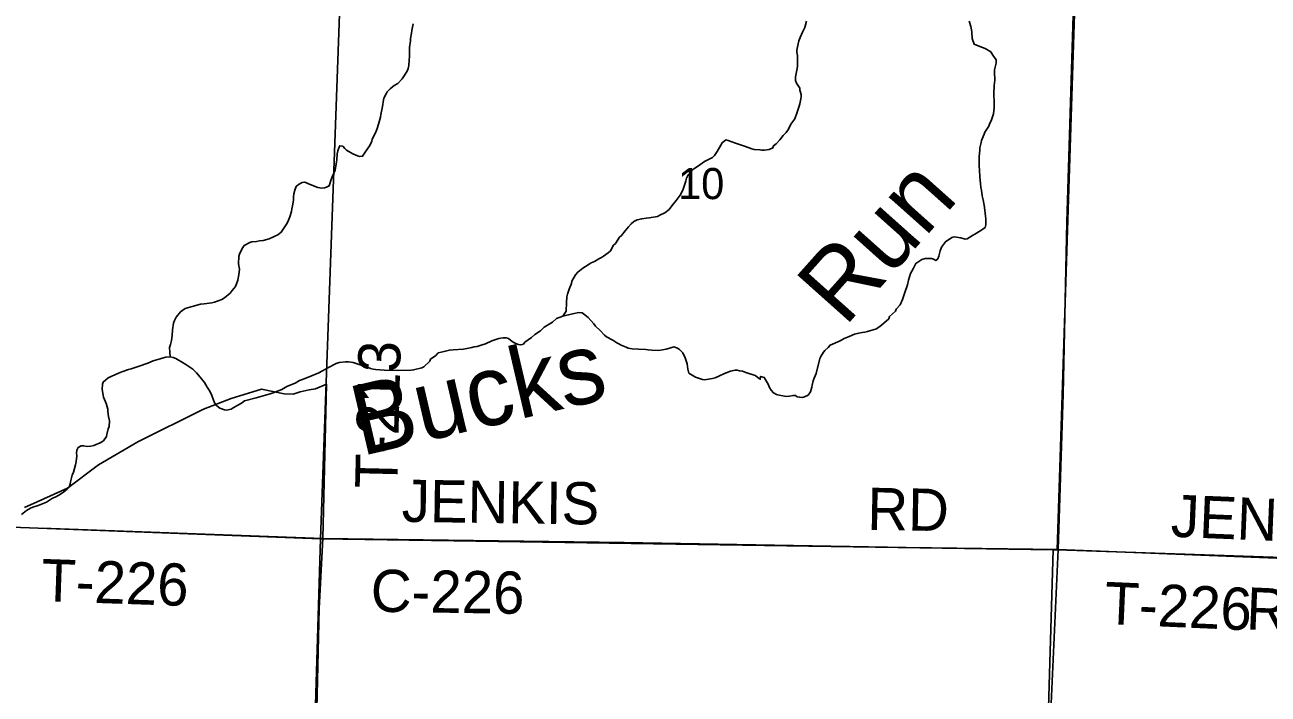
# Model space of a CAD drawing. Extents: x 1310247 to 1552180, y 377264 to 706493.
# Drawn here: x 1327940 to 1336785, y 503189 to 507946 of the extents above; entities that cross this region are included whole.
import ezdxf

# ---------------------------------------------------------------- set-up
doc = ezdxf.new("R2010")
doc.units = 0
for name, color, linetype in [('GM_X_County_Road', 7, 'Continuous'), ('GM_X_County_Road_Text', 7, 'Continuous'), ('GM_X_Minor_River', 7, 'Continuous'), ('GM_X_Minor_River_Text', 7, 'Continuous'), ('GM_X_Section', 7, 'Continuous'), ('GM_X_Section_Text', 7, 'Continuous'), ('GM_X_Township_Road', 7, 'Continuous'), ('GM_X_Township_Road_Text', 7, 'Continuous'), ('GM_X_Township_ROW', 7, 'Continuous')]:
    doc.layers.add(name, color=color, linetype=linetype)

msp = doc.modelspace()

# ---------------------------------------------------------------- linework, layer by layer
at = {"layer": 'GM_X_County_Road'}
for points in [[(1335291.7, 504215.6), (1335326.7, 505321.7), (1335352.9, 506544.2), (1335413.2, 508482.2), (1335437.6, 509275.5), (1335439.3, 509482.1)], [(1329223.9, 497744.5), (1329266.8, 497793.6), (1329294.4, 497850), (1329296.8, 497903.3), (1329271.7, 498120.6), (1329261.1, 498281.9), (1329243.9, 498488.9), (1329167.7, 498785.1), (1329133.2, 498963.3), (1329069.9, 499360.1), (1329046.9, 499679.2), (1329051.1, 499856.1), (1329091.5, 499981.1), (1329337.8, 500428), (1329828, 501332.9), (1329972.8, 501653.5), (1329996.7, 502163.8), (1330033.4, 503797.7), (1330061.2, 504294.4)], [(1330061.2, 504294.4), (1332202.8, 504267.3), (1334209, 504231.7), (1335291.7, 504215.6)], [(1334975.2, 494922.8), (1335016.7, 496120.8), (1335094.2, 499008.9), (1335141.9, 500932.5), (1335291.7, 504215.6)]]:
    msp.add_lwpolyline(points, dxfattribs=at)
at = {"layer": 'GM_X_Minor_River'}
for points in [[(1330625.5, 507563.1), (1330661.2, 507616.2), (1330667.8, 507636.1), (1330672.4, 507656), (1330675.5, 507694), (1330676.4, 507724.1), (1330675.7, 507768.2), (1330676.2, 507786.2), (1330683.6, 507832.1), (1330684, 507848.2), (1330691.2, 507888.1), (1330693.7, 507906), (1330703.2, 507953.9)], [(1331766.4, 505874.4), (1331791.6, 505911.8), (1331793.3, 505971.9), (1331796.5, 506011.9), (1331801.1, 506031.8), (1331812.1, 506067.6), (1331829.4, 506107.2), (1331831.9, 506125.1), (1331857.2, 506168.5), (1331873.9, 506188.1), (1331910.8, 506217), (1331953.8, 506245.8), (1331970.1, 506253.4), (1331992.5, 506262.7), (1332023.2, 506283.9), (1332041.5, 506291.3), (1332055.8, 506300.9), (1332090.6, 506326), (1332107.1, 506339.5), (1332128.3, 506379), (1332142.7, 506392.6), (1332170.1, 506435.9), (1332184.5, 506447.5), (1332211.5, 506480.8), (1332222, 506496.5), (1332234.5, 506510.2), (1332253.2, 506531.7), (1332273.7, 506549.1), (1332296.2, 506560.5), (1332328.5, 506567.5), (1332360.7, 506572.6), (1332380.8, 506574), (1332441.3, 506584.2), (1332457.7, 506593.7), (1332492.2, 506608.7), (1332525.1, 506633.8), (1332543.9, 506659.3), (1332573.1, 506696.6), (1332602.3, 506735.8), (1332621.4, 506771.3), (1332628.1, 506793.2), (1332632.5, 506807.1), (1332636.9, 506821), (1332641.4, 506836.9), (1332648, 506856.8), (1332658.7, 506880.5), (1332700.1, 506923.4), (1332724.6, 506938.7), (1332775.9, 506975.3), (1332794.2, 506984.8), (1332832.9, 507003.6), (1332847.3, 507017.3), (1332866.3, 507046.8), (1332891.6, 507090.1), (1332902.2, 507107.9), (1332926.9, 507129.2), (1332944.8, 507124.6), (1332996.4, 507105), (1333066, 507080.9), (1333111.7, 507065.5), (1333129.6, 507061), (1333169.6, 507057.8), (1333183.6, 507055.3), (1333201.7, 507054.8), (1333235.9, 507059.8), (1333262.3, 507071), (1333266.8, 507086.9), (1333285.3, 507100.4), (1333312.2, 507129.7), (1333335.2, 507159.1), (1333355.9, 507180.5), (1333372.6, 507204.1), (1333389.7, 507239.7), (1333416.9, 507277), (1333434.3, 507324.6), (1333449.6, 507368.2), (1333454.1, 507384.1), (1333461.2, 507420), (1333463.6, 507434), (1333464.1, 507452), (1333453, 507482.5), (1333453.4, 507496.5), (1333430.3, 507531.3), (1333422.9, 507551.5), (1333423.6, 507575.6), (1333435.4, 507635.4), (1333437.9, 507653.4), (1333437.2, 507699.5), (1333437.6, 507713.5), (1333436, 507727.6), (1333432.7, 507749.8), (1333433.1, 507765.8), (1333442.5, 507811.7), (1333447.2, 507833.6), (1333455.8, 507855.4), (1333473, 507893), (1333490, 507926.6), (1333501.4, 507972.3)], [(1334435.5, 506281.8), (1334442.1, 506301.7), (1334446.7, 506321.6), (1334451.2, 506339.5), (1334462, 506365.2), (1334489.2, 506404.5), (1334534.2, 506433.3), (1334552.4, 506438.7), (1334598.4, 506431.3), (1334630.2, 506422.4), (1334644.3, 506424), (1334681.2, 506448.9), (1334699.5, 506458.4), (1334740.4, 506485.3), (1334754.7, 506492.8), (1334771.1, 506504.4), (1334775.7, 506524.3), (1334776.9, 506566.4), (1334773.5, 506586.5), (1334767.2, 506646.9), (1334763.8, 506665.1), (1334758.8, 506701.3), (1334751.6, 506729.6), (1334746.7, 506769.9), (1334741.3, 506790.1), (1334738.1, 506818.2), (1334733.4, 506862.5), (1334730.9, 506914.7), (1334729.6, 506938.8), (1334730.5, 506968.9), (1334729.6, 507009), (1334733, 507057), (1334733.5, 507071.1), (1334742.6, 507110.9), (1334745.1, 507124.9), (1334764.4, 507168.4), (1334768.9, 507184.3), (1334798.2, 507225.6), (1334802.6, 507239.5), (1334817.6, 507271.1), (1334830.8, 507312.8), (1334836.1, 507356.8), (1334836.6, 507374.8), (1334835.5, 507403), (1334832.7, 507445.1), (1334833.1, 507459.2), (1334836.7, 507513.2), (1334839.3, 507535.2), (1334839.8, 507551.2), (1334840.4, 507573.3), (1334838.8, 507587.4), (1334837.4, 507605.5), (1334838, 507627.5), (1334849.4, 507673.3), (1334850.1, 507697.3), (1334826.9, 507730.1), (1334811.6, 507754.6), (1334772.1, 507777.9), (1334734.4, 507793), (1334692.7, 507808.3), (1334679.9, 507848.8), (1334677.2, 507893), (1334675.7, 507911.1), (1334670.3, 507933.3), (1334657.4, 507971.8)], [(1328974.3, 505585), (1328970.3, 505653.3), (1328976.9, 505673.2), (1328983.8, 505703.1), (1328988.8, 505739), (1328990, 505779.1), (1328997.3, 505825), (1329003.9, 505844.9), (1329016.7, 505868.5), (1329047.9, 505905.7), (1329080.7, 505928.8), (1329131.3, 505943.3), (1329189.9, 505959.6), (1329216.1, 505962.9), (1329270.5, 505969.2), (1329288.7, 505974.7), (1329341.4, 505993.2), (1329359.8, 506004.7), (1329401, 506039.5), (1329415.5, 506057.1), (1329438.5, 506086.5), (1329455.8, 506130.1), (1329460.6, 506156.1), (1329463, 506170), (1329466.2, 506210.1), (1329461.3, 506248.3), (1329462.8, 506300.4), (1329467.3, 506316.3), (1329486.5, 506355.9), (1329501.2, 506377.5), (1329539.9, 506398.4), (1329556.1, 506403.9), (1329588.3, 506407), (1329610.5, 506410.3), (1329636.7, 506413.5), (1329679.1, 506424.3), (1329740.2, 506452.5), (1329764.8, 506471.9), (1329783.7, 506501.4), (1329806.8, 506536.8), (1329815.4, 506556.6), (1329826.2, 506582.3), (1329837.4, 506620.1), (1329839.9, 506638.1), (1329844.6, 506660), (1329851.7, 506699.9), (1329852.4, 506723.9), (1329855, 506743.9), (1329859.9, 506771.8), (1329870.7, 506797.6), (1329887.1, 506811.1), (1329913.6, 506824.4), (1329931.7, 506827.9), (1329969.4, 506810.7), (1330024.9, 506789), (1330053, 506786.1), (1330073.1, 506787.5), (1330087.2, 506791.1), (1330105.6, 506800.6), (1330118.9, 506846.3), (1330125.5, 506866.2), (1330147, 506913.7), (1330149.4, 506927.6), (1330156.7, 506971.5), (1330159.2, 506987.5), (1330162.4, 507029.5), (1330167, 507049.4), (1330171.5, 507065.3), (1330180.1, 507087.1), (1330202.1, 507084.5), (1330215.7, 507068), (1330229.4, 507055.6), (1330257, 507038.7), (1330272.8, 507030.2), (1330306.5, 507015.2), (1330324.4, 507010.6), (1330342.5, 507012.1), (1330365.6, 507047.5), (1330394.9, 507088.7), (1330407.8, 507118.4), (1330412.3, 507134.3), (1330437.8, 507183.7), (1330446.6, 507209.5), (1330455.5, 507239.3), (1330471.1, 507291), (1330471.6, 507309), (1330482.9, 507352.8), (1330487.7, 507380.8), (1330490.3, 507398.7), (1330495, 507424.7), (1330510, 507456.3), (1330518.5, 507470.1), (1330539.1, 507491.5), (1330567.9, 507514.7), (1330594.5, 507530), (1330625.5, 507563.1)], [(1332079.2, 505728.7), (1332122.7, 505705.3), (1332136.4, 505694.9), (1332152.2, 505686.4), (1332166.1, 505677.9), (1332181.9, 505669.4), (1332217.5, 505654.3), (1332231.4, 505647.9), (1332261.4, 505643), (1332305.4, 505639.6), (1332357.6, 505638.1), (1332373.5, 505635.6), (1332399.5, 505632.8), (1332449.7, 505631.3), (1332502.1, 505639.8), (1332542.6, 505652.6), (1332556.8, 505656.2), (1332582.6, 505647.4), (1332596.4, 505639), (1332621.8, 505614.1), (1332638.8, 505579.5), (1332651.6, 505537), (1332656.5, 505498.8), (1332663.7, 505470.5), (1332711.1, 505441), (1332760.8, 505425.5), (1332774.7, 505423), (1332831.2, 505431.4), (1332851.4, 505436.8), (1332877.8, 505448), (1332916.5, 505466.9), (1332961.2, 505483.6), (1332993.5, 505490.7), (1333007.5, 505490.3), (1333023.5, 505487.8), (1333045.4, 505483.1), (1333069.3, 505474.4), (1333134.9, 505454.4), (1333154.5, 505439.7), (1333172.2, 505427.2), (1333174.8, 505447.1), (1333200.7, 505438.4), (1333229.4, 505391.4), (1333236.8, 505369.1), (1333250.2, 505348.6), (1333265.7, 505330.1), (1333287.5, 505319.4), (1333307.4, 505312.8), (1333333.3, 505308), (1333357.3, 505303.3), (1333379.5, 505306.7), (1333405.7, 505311.9), (1333421.7, 505311.4), (1333435.5, 505303), (1333453.5, 505298.4), (1333471.5, 505297.9), (1333487.7, 505301.4), (1333512.1, 505312.7), (1333528.8, 505336.3), (1333537.9, 505370.1), (1333540.3, 505384.1), (1333549.2, 505415.9), (1333555.8, 505433.7), (1333568.8, 505467.5), (1333596, 505574.9), (1333602.4, 505588.8), (1333621.4, 505618.3), (1333631.8, 505632), (1333654.5, 505653.4), (1333669, 505669), (1333740.2, 505701), (1333768.7, 505716.2), (1333805.3, 505731.1), (1333841.9, 505748.1), (1333862.1, 505751.5), (1333896.4, 505758.5), (1333916.6, 505761.9), (1333934.8, 505767.3), (1333999.5, 505785.5), (1334034.4, 505810.5), (1334085.9, 505857.1), (1334090.4, 505873), (1334133.7, 505911.8), (1334138.1, 505925.7), (1334167, 505954.9), (1334184.3, 505994.5), (1334195.3, 506030.3), (1334199.7, 506044.2), (1334219.4, 506097.8), (1334226.4, 506131.6), (1334241.8, 506179.3), (1334250.3, 506195.1), (1334263, 506216.8), (1334271.5, 506234.6), (1334278, 506250.4), (1334321, 506279.2), (1334345.2, 506284.5), (1334389.4, 506285.2), (1334405.3, 506280.7), (1334421.1, 506270.2), (1334435.5, 506281.8)], [(1328917.9, 505576.7), (1328944.2, 505583.9), (1328974.3, 505585), (1328996.2, 505580.4), (1329014.1, 505573.8), (1329037.8, 505561.1), (1329055.6, 505550.5), (1329085.1, 505531.6), (1329098.9, 505521.1), (1329134.3, 505498), (1329161.7, 505473.1), (1329186.9, 505442.3), (1329217.8, 505403.3), (1329237, 505370.6), (1329250.4, 505350.1), (1329267.5, 505317.5), (1329273.1, 505303.3), (1329280.6, 505285.1), (1329289.9, 505258.7), (1329305.3, 505238.2), (1329326.9, 505221.5), (1329360.7, 505208.5), (1329374.7, 505208), (1329407, 505215.1), (1329423.3, 505222.6), (1329460.1, 505245.6), (1329482.5, 505257), (1329503, 505272.4), (1329585.9, 505294), (1329618.4, 505305), (1329685.1, 505323.1), (1329707.4, 505330.4), (1329768.3, 505354.7), (1329805.1, 505375.6), (1329821.4, 505383.2), (1329863.9, 505397.9), (1329894.6, 505417.1), (1329908.8, 505422.7), (1329963.6, 505443.1), (1330032.7, 505473.1), (1330100, 505509.2), (1330155.1, 505539.6), (1330177.3, 505545), (1330221.6, 505549.7), (1330241.7, 505551.1), (1330275.7, 505546), (1330333.3, 505526.3), (1330353.2, 505519.7), (1330379.1, 505512.9), (1330398.9, 505504.2), (1330418.8, 505499.6), (1330434.8, 505497.1), (1330496.8, 505491.3), (1330597.1, 505488.3), (1330687.5, 505491.6), (1330705.6, 505493), (1330764.2, 505507.3), (1330778.5, 505514.9), (1330821.8, 505555.8), (1330826.3, 505569.7), (1330863.2, 505596.6), (1330881.7, 505614.1), (1330922.2, 505624.9), (1330960.6, 505633.8), (1330986.8, 505637), (1331061.1, 505640.8), (1331119.7, 505653.1), (1331137.9, 505656.6), (1331158, 505660), (1331194.5, 505670.9), (1331216.8, 505678.3), (1331261.5, 505699), (1331312.2, 505717.5), (1331326.3, 505719.1), (1331342.4, 505720.6), (1331364.5, 505722), (1331380.4, 505715.5), (1331394.2, 505705.1), (1331413.8, 505690.4), (1331437.5, 505677.7), (1331451.4, 505673.3), (1331469.4, 505670.7), (1331487.7, 505676.2), (1331498.1, 505689.9), (1331545.2, 505722.6), (1331567.9, 505744), (1331608.8, 505770.8), (1331635.6, 505796.1), (1331692.9, 505832.5), (1331721.7, 505857.7), (1331766.4, 505874.4), (1331837.1, 505892.3), (1331881.6, 505901), (1331905.5, 505898.3), (1331925.2, 505883.7), (1331948.8, 505866.9), (1331987.6, 505821.6), (1331999.1, 505803.3), (1332032.4, 505774.2), (1332063.5, 505739.2), (1332079.2, 505728.7)], [(1327916.1, 504465.6), (1327953, 504494.5), (1327981.6, 504509.7), (1327997.9, 504517.3), (1328034.3, 504528.2), (1328095.2, 504552.5), (1328138.2, 504581.3), (1328156.5, 504588.7), (1328187.1, 504605.9), (1328217.8, 504627), (1328242.4, 504644.3), (1328254.9, 504660), (1328261.6, 504681.8), (1328264, 504697.8), (1328277.5, 504745.5), (1328286.1, 504765.3), (1328301.7, 504819), (1328306.4, 504843), (1328309.6, 504883), (1328308.1, 504901.1), (1328310.7, 504923), (1328319.4, 504942.8), (1328341.8, 504954.2), (1328357.8, 504953.7), (1328383.8, 504948.9), (1328409.9, 504952.2), (1328430.1, 504955.6), (1328476.8, 504974.2), (1328499.3, 504989.6), (1328520.3, 505019), (1328524.7, 505033), (1328533.9, 505074.8), (1328540.4, 505090.6), (1328541.6, 505130.7), (1328536.4, 505161), (1328531.5, 505197.2), (1328529.9, 505213.3), (1328520.9, 505247.7), (1328513.4, 505265.9), (1328500.3, 505298.4), (1328496.7, 505312.6), (1328489.9, 505354.9), (1328493, 505390.9), (1328497.5, 505406.8), (1328532.5, 505437.8), (1328605.7, 505469.7), (1328630, 505479), (1328678.7, 505495.6), (1328696.9, 505501.1), (1328753.6, 505519.5), (1328814.5, 505541.7), (1328853.1, 505558.6), (1328869.3, 505562.1), (1328903.6, 505571.1), (1328917.9, 505576.7)]]:
    msp.add_lwpolyline(points, dxfattribs=at)
at = {"layer": 'GM_X_Section'}
for points in [[(1324992.2, 509766.5), (1330233.2, 509528.3), (1330044.5, 504292.3), (1324834.5, 504489.4)], [(1330233.2, 509528.3), (1335454.8, 509493.8), (1335284.2, 504214.1), (1335256.2, 504214.7), (1330044.5, 504292.3)], [(1340611.4, 509318.9), (1340450.8, 504038.6), (1335284.2, 504214.1), (1335454.8, 509493.8)], [(1324834.5, 504489.4), (1330044.5, 504292.3), (1329885.7, 499025.1), (1324675.2, 499184.9)], [(1330044.5, 504292.3), (1335256.2, 504214.7), (1335099.6, 498913.7), (1329885.7, 499025.1)], [(1335256.2, 504214.7), (1335284.2, 504214.1), (1340450.8, 504038.6), (1340312, 498733.1), (1335099.6, 498913.7)]]:
    msp.add_lwpolyline(points, close=True, dxfattribs=at)
at = {"layer": 'GM_X_Township_Road'}
for points in [[(1330061.2, 504294.4), (1330086.3, 505392.9)], [(1328063.4, 504367.5), (1330061.2, 504294.4)], [(1335291.7, 504215.6), (1336904.9, 504151.6), (1337870.1, 504113.8)]]:
    msp.add_lwpolyline(points, dxfattribs=at)
at = {"layer": 'GM_X_Township_ROW'}
msp.add_lwpolyline([(1327937.9, 504515.2), (1328028.4, 504554.7), (1328244.2, 504653.4), (1328463.2, 504819.1), (1328745.2, 504980.9), (1329210.4, 505213.8), (1329408.3, 505288.8), (1329623, 505355.9), (1329785.1, 505324.3), (1329848.2, 505319.6), (1329898, 505337), (1329962.5, 505351), (1330008.6, 505359.4), (1330086.3, 505392.9)], dxfattribs=at)

# ---------------------------------------------------------------- texts
at = {"layer": 'GM_X_County_Road_Text'}
for s, rotation, p in [('JENKIS', 359.17572, (1330620.2, 504413.7)), ('RD', 359.02071, (1333932.1, 504356.4)), ('C-226', 359.1736, (1330399.8, 503774.5))]:
    msp.add_text(s, height=300, rotation=rotation, dxfattribs=at).set_placement(p)
at = {"layer": 'GM_X_Minor_River_Text'}
for s, height, rotation, p in [('Run', 499.97, 48.27943, (1333773, 505793.1)), ('Bucks', 499.99, 13.14979, (1330332.9, 504879.1))]:
    msp.add_text(s, height=height, rotation=rotation, dxfattribs=at).set_placement(p)
at = {"layer": 'GM_X_Section_Text'}
msp.add_text('10', height=221, rotation=0.00001, dxfattribs=at).set_placement((1332587.5, 506707.2))
at = {"layer": 'GM_X_Township_Road_Text'}
for s, rotation, p in [('T-213', 88.59593, (1330589.1, 504648.1)), ('JENKINS', 357.6283, (1336089.5, 504308)), ('T-226', 358.03475, (1328053.1, 503850.1)), ('T-226', 357.47367, (1335616, 503687.5)), ('RD', 357.5319, (1336624.9, 503648.7))]:
    msp.add_text(s, height=300, rotation=rotation, dxfattribs=at).set_placement(p)

doc.saveas('drawing.dxf')
